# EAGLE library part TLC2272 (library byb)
Dual Operational Amplifier Low Power, Single-Supply, Rail-To-Rail Operational Amplifier Source: http://focus.ti.com/lit/ds/symlink/opa2345.pdf http://focus.ti.com .. opa241.pdf http://focus.ti.com/lit/ds/symlink/opa2134.pdf
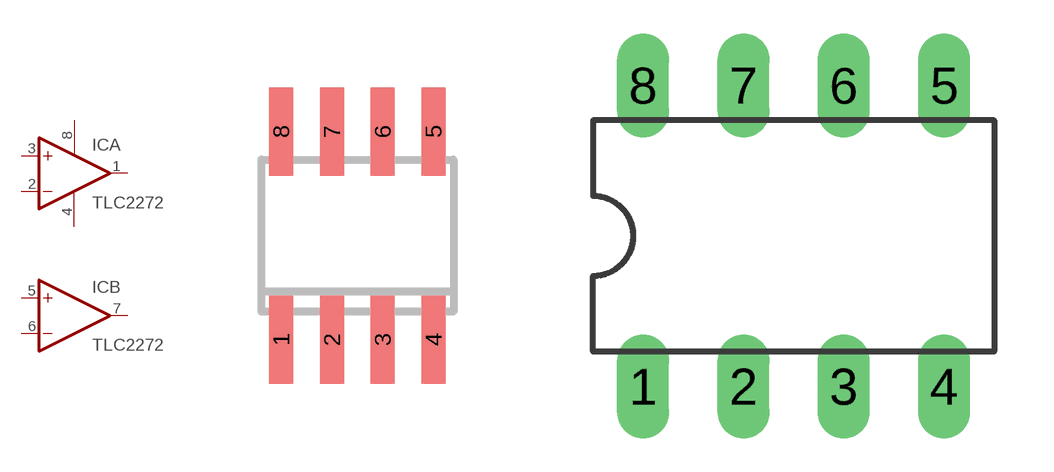
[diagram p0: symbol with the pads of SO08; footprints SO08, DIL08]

Designator prefix IC; gates A=OPAMP+- B=OPAMP

## TLC2272344U, TLC2272345U  [SO08]
1  A:OUT  out
2  A:-IN  in
3  A:+IN  in
4  A:V-  pwr
5  B:+IN  in
6  B:-IN  in
7  B:OUT  out
8  A:V+  pwr

## TLC2272344P  [DIL08]
Pads as for SO08

## Footprint SO08 (pad centres in mm)
Small Outline Package 8 NS Package M08A
smd 0.6 x 2.2: 1 -1.905,-2.6; 2 -0.635,-2.6; 3 0.635,-2.6; 4 1.905,-2.6; 5 1.905,2.6; 6 0.635,2.6; 7 -0.635,2.6; 8 -1.905,2.6

## Footprint DIL08 (pad centres in mm)
Dual In Line Package
drill 0.813 pad 1.27 long: 1 -3.81,-3.81; 2 -1.27,-3.81; 3 1.27,-3.81; 4 3.81,-3.81; 5 3.81,3.81; 6 1.27,3.81; 7 -1.27,3.81; 8 -3.81,3.81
